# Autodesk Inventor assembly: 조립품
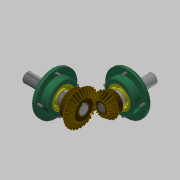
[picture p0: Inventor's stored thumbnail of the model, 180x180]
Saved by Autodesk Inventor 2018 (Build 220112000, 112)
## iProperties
Created: 2023-01
Part Number: 조립품
Material: 일반
Document SubType Name: Assembly
Designer: home
Author: home
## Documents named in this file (14)
- C:\Users\home\Desktop\730106V1007\조립품.iam
- C:\Users\home\Desktop\730106V1007\본체.ipt
- C:\Users\home\Desktop\730106V1007\커버.ipt
- C:\Users\home\Desktop\730106V1007\베어링 6203.ipt
- C:\Users\home\Desktop\730106V1007\메인 축.ipt
- 메인 축.ipt
- C:\Users\home\Desktop\730106V1007\서브 축.ipt
- 서브 축.ipt
- C:\Users\home\Desktop\730106V1007\메인 베벨기어.ipt
- C:\Users\home\Desktop\730106V1007\키 5x5.ipt
- C:\Users\home\Desktop\730106V1007\서브 베벨기어.ipt
- C:\Users\home\Desktop\730106V1007\키 4x4.ipt
- C:\Users\home\Desktop\730106V1007\오일실 17 32 8.ipt
- C:\Users\home\Desktop\730106V1007\M4.ipt
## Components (8 placed, 1 different names)
1. M4:1
2. M4:3
3. M4:4
4. M4:5
5. M4:2
6. M4:6
7. M4:7
8. M4:8
